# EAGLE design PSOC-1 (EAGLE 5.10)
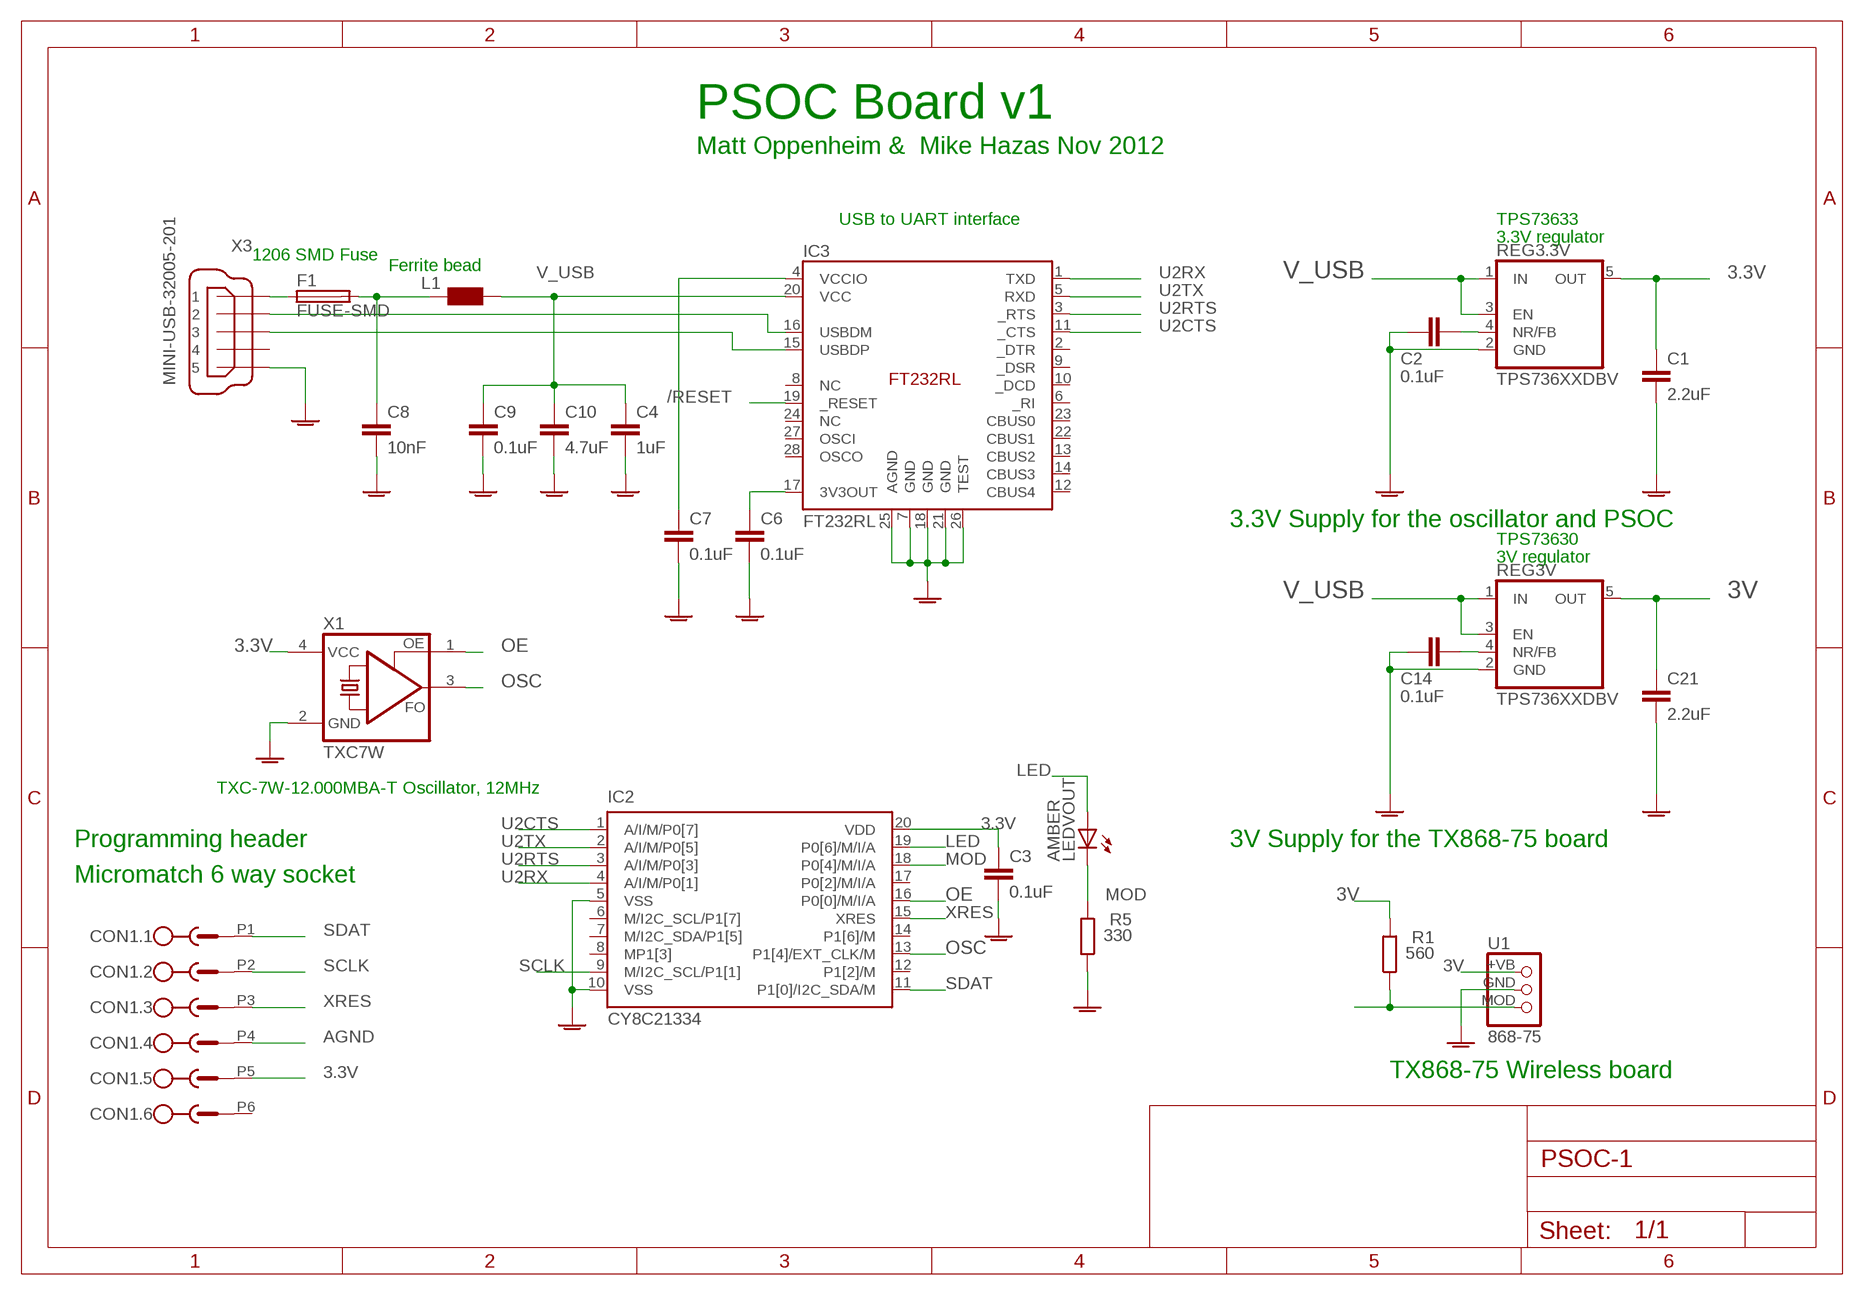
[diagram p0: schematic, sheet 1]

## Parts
C1  2.2uF  C-EUC0603  [C0603]
C2  0.1uF  C-EUC0603  [C0603]
C3  0.1uF  C-EUC0603  [C0603]
C4  1uF  C-EUC0603  [C0603]
C6  0.1uF  C-EUC0603  [C0603]
C7  0.1uF  C-EUC0603  [C0603]
C8  10nF  C-EUC0603  [C0603]
C9  0.1uF  C-EUC0603  [C0603]
C10  4.7uF  C-EUC0603  [C0603]
C14  0.1uF  C-EUC0603  [C0603]
C21  2.2uF  C-EUC0603  [C0603]
CON1  MICROMATCH_6TH  [MICROMATCH-6H]
F1  FUSE-SMD  [C1206]
IC2  CY8C21334  [SSOP20]
IC3  FT232RL  [SSOP-28]
L1  WE-CBF_0603  [0603]
LEDVOUT  AMBER  LEDCHIP-LED0805  [CHIP-LED0805]
R1  560  R-EU_R0603  [R0603]
R5  330  R-EU_R0603  [R0603]
REG3.3V  TPS736XXDBV  [SOT23-5L]
REG3V  TPS736XXDBV  [SOT23-5L]
U1  868-75  [868-75]
X1  TXC7W  [7W-24]
X3  MINI-USB-32005-201  [32005-201]

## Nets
3.3V: C1.1 C3.1 CON1.P5 IC2.20(VDD) REG3.3V.5(OUT) X1.4(VCC)
3V: C21.1 R1.2 REG3V.5(OUT) U1.+VB
/RESET: IC3.19(_RESET)
AGND: C1.2 C2.1 C3.2 C4.2 C6.2 C7.2 C8.2 C9.2 C10.2 C14.1 C21.2 CON1.P4 IC2.5(VSS) IC2.10(VSS) IC3.7(GND) IC3.18(GND) IC3.21(GND) IC3.25(AGND) IC3.26(TEST) R5.1 REG3.3V.2(GND) REG3V.2(GND) U1.GND X1.2(GND) X3.5
LED: IC2.19(P0[6]/M/I/A) LEDVOUT.A
MOD: IC2.18(P0[4]/M/I/A) R1.1 U1.MOD
N$1: C2.2 REG3.3V.4(NR/FB)
N$2: IC3.16(USBDM) X3.2
N$3: C6.1 IC3.17(3V3OUT)
N$5: F1.1 X3.1
N$8: C7.1 IC3.4(VCCIO)
N$13: IC3.15(USBDP) X3.3
N$14: C8.1 F1.2 L1.1
N$21: LEDVOUT.C R5.2
N$28: C14.2 REG3V.4(NR/FB)
OE: IC2.16(P0[0]/M/I/A) X1.1(OE)
OSC: IC2.13(P1[4]/EXT_CLK/M) X1.3(FO)
SCLK: CON1.P2 IC2.9(M/I2C_SCL/P1[1])
SDAT: CON1.P1 IC2.11(P1[0]/I2C_SDA/M)
U2CTS: IC2.1(A/I/M/P0[7]) IC3.11(_CTS)
U2RTS: IC2.3(A/I/M/P0[3]) IC3.3(_RTS)
U2RX: IC2.4(A/I/M/P0[1]) IC3.1(TXD)
U2TX: IC2.2(A/I/M/P0[5]) IC3.5(RXD)
V_USB: C4.1 C9.1 C10.1 IC3.20(VCC) L1.2 REG3.3V.1(IN) REG3.3V.3(EN) REG3V.1(IN) REG3V.3(EN)
XRES: CON1.P3 IC2.15(XRES)
Unconnected: CON1.P6 IC2.6(M/I2C_SCL/P1[7]) IC2.7(M/I2C_SDA/P1[5]) IC2.8(MP1[3]) IC2.12(P1[2]/M) IC2.14(P1[6]/M) IC2.17(P0[2]/M/I/A) IC3.2(_DTR) IC3.6(_RI) IC3.8(NC) IC3.9(_DSR) IC3.10(_DCD) IC3.12(CBUS4) IC3.13(CBUS2) IC3.14(CBUS3) IC3.22(CBUS1) IC3.23(CBUS0) IC3.24(NC) IC3.27(OSCI) IC3.28(OSCO) X3.4

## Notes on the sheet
- PSOC Board v1
- Matt Oppenheim &  Mike Hazas Nov 2012
- USB to UART interface | TPS73633
- 3.3V regulator
- 1206 SMD Fuse | Ferrite bead
- 3.3V Supply for the oscillator and PSOC
- TPS73630
- 3V regulator
- TXC-7W-12.000MBA-T Oscillator, 12MHz
- Programming header | 3V Supply for the TX868-75 board
- Micromatch 6 way socket
- TX868-75 Wireless board

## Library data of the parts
C1-C4 C6-C10 C14 C21 = rcl:C-EU: CAPACITOR, European symbol
CON1 = con-Micromatch:MICROMATCH_6: MicroMatch 6 way
F1 = Fuse:FUSE-SMD: Surface mount fuse.
IC2 = cypress:CY8C21334: PSoC® Programmable System-on-Chip? M8C Processor Speeds to 24 MHz Source: http://www.cypress.com .. 38-12025_0P_V.pdf
IC3 = ftdi4:FT232RL
L1 = wuerth-elektronik:WE-CBF: SMD EMI Suppression Ferrite Beads
LEDVOUT = led:LED: LED
R1 R5 = rcl:R-EU_: RESISTOR, European symbol
REG3.3V REG3V = Cube:TPS736XX*: VOLTAGE REGULATOR Texas Instruments low dropout 0.4A regulator, fixed and adjustable.
U1 = ELV:868-75: RF transmitter, used by Mike Hazas for energy monitoring hardware. Datasheet (in German): http://www.elv-downloads.de/service/manuals/TX868_75/TX868_75_UM_G_080519.pdf
X1 = Oscillator:TXC7W: TXC 7W SMD Oscillator Farnell part 1842107 24MHz
X3 = con-cypressindustries:MINI-USB-: MINI USB-B Conector Source: www.cypressindustries.com

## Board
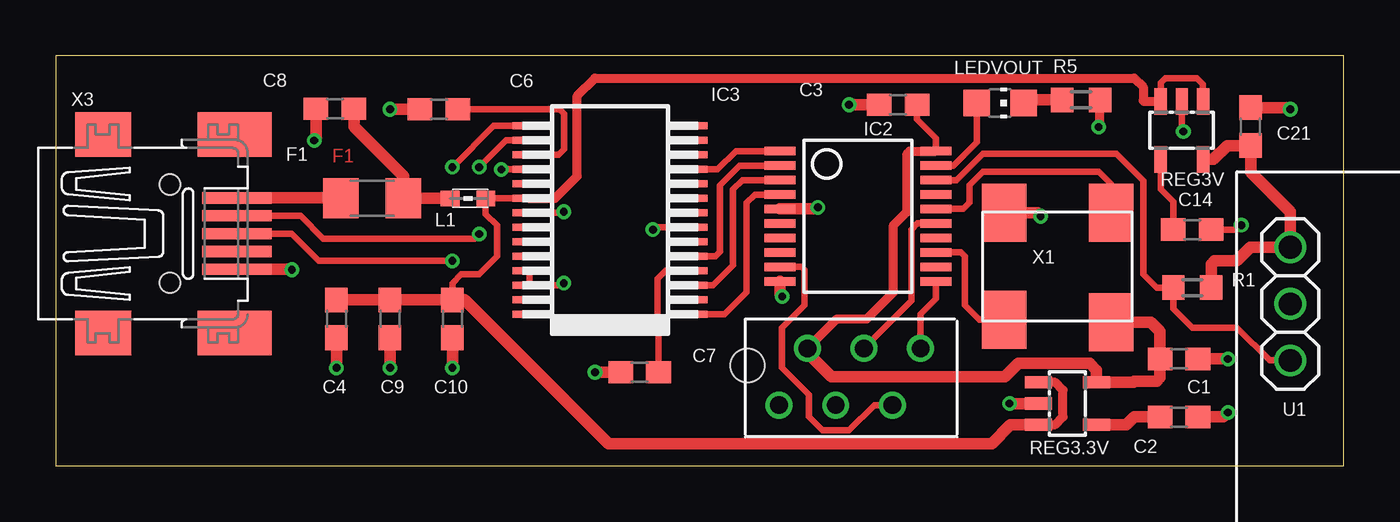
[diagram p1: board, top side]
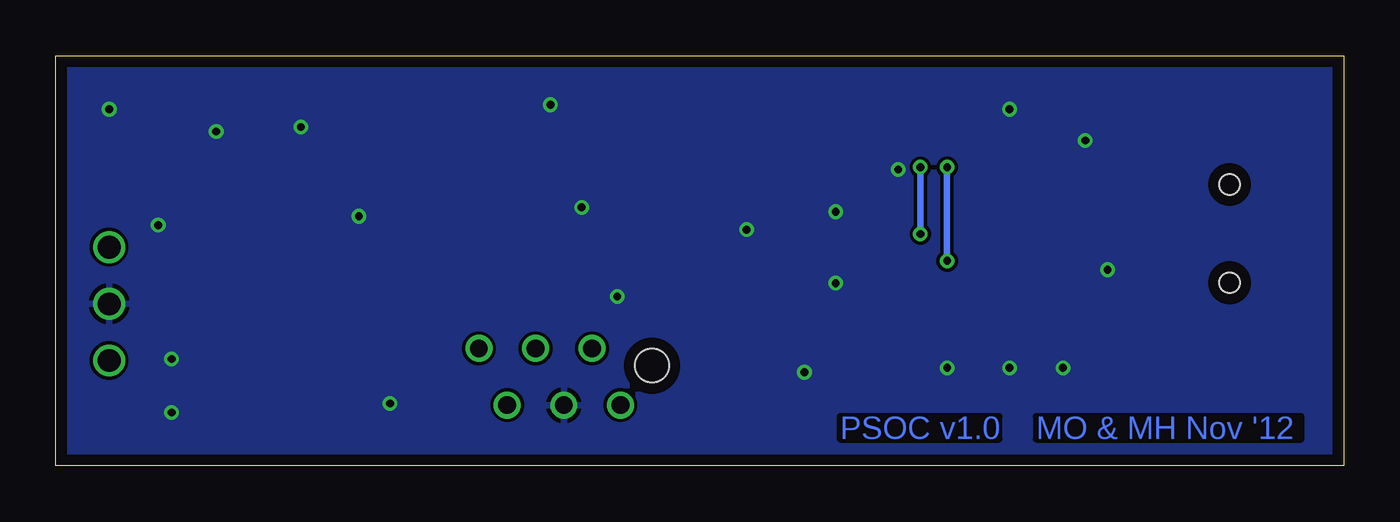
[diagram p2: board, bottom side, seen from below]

Size 57.8 x 18.4 mm. Coordinates in mm from the lower left corner, seen from the top.
Outline: 0,0 57.8,0 57.8,18.4 0,18.4 0,0
Copper layers (1*16): Top 0.035mm / dielectric 1.5mm / Bottom 0.035mm
Design rules "PCB-POOL - 2 layer, edited": minimum track width 6mil, minimum drill 12mil, track to track 6mil, track to pad 8mil, pad to pad 6mil, via to via 6mil, smd to smd 6mil, copper to edge 20mil, drill to drill 8mil, minimum pad ring 8mil, minimum via ring 6mil, stop-mask expansion 3mil, vias tented up to drill 0.35mm, thermal gap 8mil

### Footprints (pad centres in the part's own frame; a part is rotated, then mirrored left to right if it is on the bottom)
C0603 = smd 1.1 x 1: 1 -0.85,0; 2 0.85,0
MICROMATCH-6H = drill 0.8 round: P1 -3.81,-1.27; P2 -2.54,1.27; P3 -1.27,-1.27; P4 0,1.27; P5 1.27,-1.27; P6 2.54,1.27 | hole 1.5: 3.96,-0.5
C1206 = smd 1.6 x 1.8: 1 -1.4,0; 2 1.4,0
SSOP20 = smd 0.38 x 1.4: 1 -2.925,-3.5; 2 -2.275,-3.5; 3 -1.625,-3.5; 4 -0.975,-3.5; 5 -0.325,-3.5; 6 0.325,-3.5; 7 0.975,-3.5; 8 1.625,-3.5; 9 2.275,-3.5; 10 2.925,-3.5; 11 2.925,3.5; 12 2.275,3.5; 13 1.625,3.5; 14 0.975,3.5; 15 0.325,3.5; 16 -0.325,3.5; 17 -0.975,3.5; 18 -1.625,3.5; 19 -2.275,3.5; 20 -2.925,3.5
SSOP-28 = smd 0.3 x 1.5: 1 -4.225,-3.625; 2 -3.575,-3.625; 3 -2.925,-3.625; 4 -2.275,-3.625; 5 -1.625,-3.625; 6 -0.975,-3.625; 7 -0.325,-3.625; 8 0.325,-3.625; 9 0.975,-3.625; 10 1.625,-3.625; 11 2.275,-3.625; 12 2.925,-3.625; 13 3.575,-3.625; 14 4.225,-3.625; 15 4.225,3.625; 16 3.575,3.625; 17 2.925,3.625; 18 2.275,3.625; 19 1.625,3.625; 20 0.975,3.625; 21 0.325,3.625; 22 -0.325,3.625; 23 -0.975,3.625; 24 -1.625,3.625; 25 -2.275,3.625; 26 -2.925,3.625; 27 -3.575,3.625; 28 -4.225,3.625
0603 = smd 0.85 x 0.7: 1 -0.9,0; 2 0.7,0
CHIP-LED0805 = smd 1.2 x 1.2: A 0,-1.05; C 0,1.05
R0603 = smd 1 x 1.1: 1 -0.85,0; 2 0.85,0
SOT23-5L = smd 0.55 x 1.2: 1 -0.95,-1.3; 2 0,-1.3; 3 0.95,-1.3; 4 0.95,1.3; 5 -0.95,1.3
868-75 = drill 1.016 round: +VB 2.4,22.61; GND 2.4,20.07; MOD 2.4,17.53
7W-24 = smd 2 x 2.6: 1 1.05,1.25; 2 5.85,1.25; 3 5.85,6.05; 4 1.05,6.15
32005-201 = smd 3.1 x 0.5: 1 3,1.6; 2 3,0.8; 3 3,0; 4 3,-0.8; 5 3,-1.6 | smd 2.5 x 2: M1 -3,-4.45; M2 -3,4.45 | smd 3.3 x 2: M3 2.9,4.45; M4 2.9,-4.45 | hole 0.9: 0,2.2; 0,-2.2

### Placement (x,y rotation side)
C1  50.4,4.8 0 top
C2  50.4,2.2 180 top
C3  37.8,16.2 180 top
C4  12.6,6.6 270 top
C6  17.2,16 180 top
C7  26.2,4.2 180 top
C8  12.53,16.02 180 top
C9  15,6.6 270 top
C10  17.8,6.6 270 top
C14  51,10.6 180 top
C21  53.62,15.22 90 top
CON1  35,4 180 top
F1  14.2,12 0 top
IC2  36,11.2 270 top
IC3  24.88,11.03 90 top
L1  18.6,12 0 top
LEDVOUT  42.38,16.28 270 top
R1  51,8 0 top
R5  46.01,16.42 180 top
REG3.3V  45.4,2.8 270 top
REG3V  50.53,15.05 180 top
U1  53,-12.8 0 top
X1  48.4,12.6 180 top
X3  5.13,10.42 0 top

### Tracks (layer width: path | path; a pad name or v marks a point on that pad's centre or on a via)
3.3V
  Top 0.3: C3.1 38.65,15.55 39.5,14.7 IC2.20
  Top 0.4: IC2.20 38.33,14.12 38.2,14 38.2,11.4 37.6,10.8 37.6,7.8 36.4,6.6 35.06,6.6 CON1.P5
  Top 0.508: CON1.P5 33.73,5.07 34.8,4 42.6,4 43.2,4.6 46.4,4.6 46.7,4.3 REG3.3V.5 48.35,3.75 48.4,3.8 49.4,3.8 49.55,3.95 C1.1 49.55,6.05 49.15,6.45 X1.4
3V
  Top 0.508: REG3V.5 51.95,13.75 52.57,14.37 C21.1 53.62,13.18 55.4,11.4 U1.+VB 53.61,9.81 53,9.2 52,9.2 51.85,9.05 R1.2
AGND  (via drill 0.35)
  Top 0.3: IC3.7 26.91,10.71 v26.8,10.6 | 34.12,11.53 v34.2,11.6 | 10.58,8.82 v10.6,8.8 | v22.8,8.2 22.89,8.11 IC3.26 IC3.25 | IC3.18 19.91,13.3 v20,13.3 | 55.33,16.07 v55.4,16 | C14.1 53,10.6 v53.2,10.8 | REG3V.2 50.53,15.07 v50.6,15 | IC3.21 22.75,11.36 v22.8,11.4
  Top 0.4: R5.1 46.86,15.26 v46.8,15.2
  Top 0.508: IC2.5 34.12,11.53 | IC2.10 32.5,7.7 v32.6,7.6 | v12.6,4.4 C4.2 | v15,4.4 C9.2 | v17.8,4.4 C10.2 | X3.5 10.58,8.82 | C7.2 v24.2,4.2 | C1.2 v52.6,4.8 | C2.1 52.4,2.2 v52.6,2.4 | C3.2 v35.6,16.2 | C21.2 55.33,16.07 | C8.2 11.68,14.68 v11.6,14.6 | v15,16 C6.2 | X1.2 44.05,11.35 v44.2,11.2 | v42.8,2.8 REG3.3V.2
  pour Bottom: 0.4,18.2 57.4,18.2 57.2,0.2 0.4,0.4
LED
  Top 0.3: IC2.19 40.27,13.47 41.33,14.53 LEDVOUT.A
MOD
  Top 0.3: U1.MOD 54.47,4.73 53,6.2 51,6.2 50.15,7.05 R1.1 49.4,8 48.8,8.6 48.8,12.8 47.6,14 41.6,14 40.42,12.82 IC2.18
N$1
  Top 0.508: C2.2 48.4,2.2 48.05,1.85 REG3.3V.4
N$2  (via drill 0.35)
  Top 0.3: IC3.16 20.2,14.61 v19,13.4 | X3.2 10.98,11.22 12,10.2 18.8,10.2 v19,10.4
  Bottom 0.3: v19,10.4 v19,13.4
N$3
  Top 0.3: C6.1 22.6,16 22.8,15.8 22.8,14.2 22.55,13.96 IC3.17
N$5
  Top 0.508: X3.1 12.98,12.02
  Top 0.6: 12.98,12.02 F1.1
N$8
  Top 0.3: IC3.4 27.36,8.76 27,8.4 27,6 27.05,5.95 C7.1
N$13  (via drill 0.35)
  Top 0.3: IC3.15 19.66,15.26 v17.8,13.4 | X3.3 10.58,10.42 11.8,9.2 v17.8,9.2
  Bottom 0.3: v17.8,9.2 v17.8,13.4
N$14
  Top 0.508: L1.1 F1.2 15.6,13 13.38,15.22 C8.1
N$21
  Top 0.508: R5.2 43.57,16.42 LEDVOUT.C
N$28
  Top 0.3: REG3V.4 49.58,12.42 50.15,11.85 C14.2
OE
  Top 0.3: X1.1 47.35,12.65 46.8,13.2 41.6,13.2 41,12.6 41,11.8 40.73,11.53 IC2.16
OSC
  Top 0.3: IC2.13 40.62,9.57 40.8,9.4 40.8,7.2 41.45,6.55 X1.3
SCLK
  Top 0.3: IC2.9 33.48,8.93 33.6,8.8 33.6,7.2 32.6,6.2 32.6,4.4 33.8,3.2 33.8,2.2 34.4,1.6 35.6,1.6 36.73,2.73 CON1.P2
SDAT
  Top 0.3: CON1.P1 38.81,6.81 39.5,7.5 IC2.11
U2CTS
  Top 0.3: IC3.11 29.7,13.3 30.52,14.12 IC2.1
U2RTS
  Top 0.3: IC3.3 29.5,8.11 30.4,9 30.4,12.4 30.82,12.82 IC2.3
U2RX
  Top 0.3: IC3.1 30,6.8 31,7.8 31,11.8 31.38,12.18 IC2.4
U2TX
  Top 0.3: IC3.5 29.61,9.4 29.8,9.6 29.8,12.6 30.68,13.47 IC2.2
V_USB
  Top 0.3: IC3.20 L1.2 19.3,11.3 19.8,10.8 19.8,9.4 19,8.6 18.2,8.6 17.8,8.2 C10.1 | REG3V.3 49.58,17.18 49.8,17.4 51.2,17.4 51.48,17.12 REG3V.1
  Top 0.4: IC3.20 22.41,12.01 23.4,13 23.4,16.6 24.2,17.4 48.4,17.4 48.8,17 48.8,16.4 48.85,16.35 REG3V.3 | REG3.3V.1 44.85,3.75 45.2,3.4 45.2,2.2 44.85,1.85 REG3.3V.3
  Top 0.508: C4.1 C9.1 C10.1 18.35,7.45 24.8,1 42,1 42.85,1.85 REG3.3V.3
XRES
  Top 0.3: IC2.15 38.67,10.88 38.4,10.6 38.4,7.4 CON1.P3

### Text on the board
Top: F1
Bottom: MO & MH Nov '12 | PSOC v1.0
